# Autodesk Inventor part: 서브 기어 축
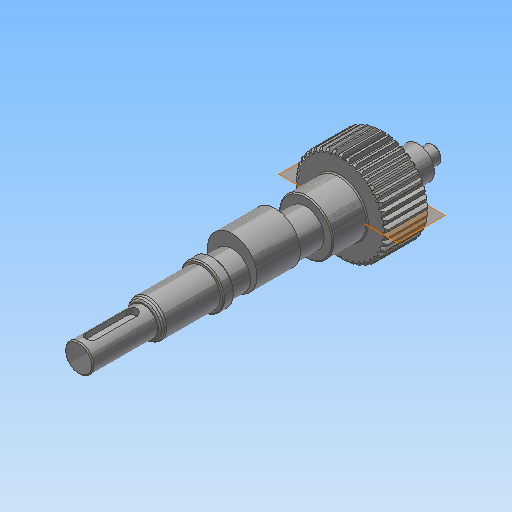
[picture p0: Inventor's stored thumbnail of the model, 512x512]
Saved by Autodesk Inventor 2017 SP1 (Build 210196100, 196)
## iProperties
Created: 2018-12
Part Number: 서브 기어 축
Material: 강철, 연강
Document SubType Name: Modeling
Designer: mduedu
Categories: <?xml version="1.0" encoding="UTF-16"?> <MemberInstance><Categories><FamilyTemplate><FamilyTemplateParameter ValueType="xs:double" Id="1" ObjectReferenceKey="da
Density: 1 g/cm^3
Appearance: 강철
Author: mduedu
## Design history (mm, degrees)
sketch "Sketch1"
  geometry: C1 r 21.3 at (0, 0)
  constraints: 1 centre point
  dimensions: "d0" = 42.6 diameter of C1 (= da_da)
extrude "Extrusion1" new body sketch "Sketch1" distance "d1" = 20 (= da_b); taper "d2" = 0 deg
workplane "Work Plane2"
sketch "Sketch2"
  geometry: C1 r 21.3 at (0, 0) reference; C2 r 20.5 at (0, 0)
  constraints: 1 centre point, 1 coincident
  dimensions: "d3" = 41 diameter of C2 (= da_dw)
feature "피치 지름" sketch "Sketch2" dims "d4" = 10, "d5" = 0
workplane "Work Plane8"
workplane "Work Plane9"
chamfer "모따기1" distance "d49" = 1; stored, may be unused: second distance "d50" = 2, angle "d51" = 45 deg
sketch "스케치3"
  geometry: C1 r 12.5 at (0, 0); 1 further point
  constraints: 1 centre point, 1 coincident
  dimensions: "d52" = 25 diameter of C1
extrude "돌출2" join sketch "스케치3" distance "d53" = 16; taper "d54" = 0 deg
sketch "스케치4"
  geometry: C1 r 8.5 at (0, 0); 1 further point
  constraints: 1 centre point, 1 coincident
  dimensions: "d55" = 17 diameter of C1
extrude "돌출3" join sketch "스케치4" distance "d56" = 105; taper "d57" = 0 deg
sketch "스케치5"
  geometry: C1 r 7.5 at (0, 0); 1 further point
  constraints: 1 centre point, 1 coincident
  dimensions: "d58" = 15 diameter of C1
extrude "돌출4" join sketch "스케치5" distance "d59" = 16; taper "d60" = 0 deg
sketch "스케치6"
  geometry: C1 r 4 at (0, 0); 1 further point
  constraints: 1 centre point, 1 coincident
  dimensions: "d61" = 8 diameter of C1
extrude "돌출5" join sketch "스케치6" distance "d62" = 7; taper "d63" = 0 deg
fillet "모깎기1" dims "d67" = 0.5
feature "스퍼 기어" dims "da_b" = 20, "da_d" = 41, "da_aw" = 31, "da_da" = 42.6, "da_df" = 39.086, "da_dw" = 41, angle "da_beta" = 0 deg, "da_lefttooth" = 0, "da_righttooth" = 0
node "작업 평면11"
sketch "스케치7"
  geometry: C1 r 11.5 at (0, 3); C2 r 8.5 at (0, 0) reference; 1 further point
  constraints: 1 centre point, 1 tangent, 1 vertical alignment
  dimensions: "d69" = 3 distance of point (0, 0) C1.centre; "d70" = 23 diameter of C1 (derived)
extrude "돌출6" join sketch "스케치7" stored distance "d71" = 20; taper "d72" = 0 deg
node "작업 평면12"
sketch "스케치8"
  geometry: C1 r 12.5 at (0, 0) reference; C2 r 10 at (0, 0); 1 further point
  constraints: 1 centre point, 1 coincident
  dimensions: "d110" = 20 diameter of C2
extrude "돌출7" join sketch "스케치8" distance "d74" = 5; taper "d75" = 0 deg
sketch "스케치14"
  geometry: L1 (-11.5, 111)-(-6.5, 111); L2 (-6.5, 111)-(-6.5, 141); L3 (-6.5, 141)-(-11.5, 141); L4 (-11.5, 141)-(-11.5, 111); L5 (8.5, 141)-(-8.5, 141) reference; L6 (0, 0)-(0, 141)
  constraints: 10 end point, 2 parallel, 1 collinear, 1 horizontal, 1 midpoint, 1 perpendicular
  dimensions: "d92" = 30 distance between parallel lines of L1 L5; "d93" = 13 diameter of L2 L6; "d95" = 5 distance of L2.end L3.end
revolve "회전2" sketch "스케치14" stored, may be unused: angle "d96" = 90 deg
chamfer "모따기4" distance "d97" = 0.5; stored, may be unused: second distance "d98" = 2, angle "d99" = 45 deg
revolve "회전1" stored, may be unused: angle "d82" = 90 deg
sketch "스케치10"
  geometry: L1 (-6.5, 117.5)-(-5, 116) reference; L2 (-6.5, 114.5)-(-5, 116) reference; 2 further points
  constraints: 1 coincident
node "작업점1"
node "작업 평면13"
sketch "스케치11"
  geometry: L1 (-2.5, 9.5)-(-2.5, -9.5); L2 (2.5, -9.5)-(2.5, 9.5); L3 (-6, 15)-(6, 15) reference; A1 r 2.5 centre (0, 9.5) between (2.5, 9.5) and (-2.5, 9.5); A2 r 2.5 centre (0, -9.5) between (-2.5, -9.5) and (2.5, -9.5); 1 further point
  constraints: 4 end point, 4 point on circle, 4 tangent, 2 centre point, 2 vertical alignment, 1 parallel
  dimensions: "d84" = 24 dimension on A2 A1; "d85" = 5 distance between parallel lines of L1 L2; "d108" = 3 distance edge to line of A1 L3
extrude "돌출8" cut sketch "스케치11" distance "d86" = 3; taper "d87" = 0 deg
sketch "스케치12" dims "d88" = 32
  geometry: C1 r 0.5 at (0, -16); 2 further points
  constraints: 2 vertical alignment, 1 centre point, 1 coincident, 2 other
  dimensions: "d89" = 1 diameter of C1
extrude "돌출9" join sketch "스케치12" distance "d90" = 0.3; taper "d91" = 0 deg
sketch "스케치13"
  geometry: C1 r 11.5 at (0, 3) reference; 1 further point
  node "절단 모서리 투영1"
sketch "스케치15"
  geometry: L1 (-8.5, 109.181)-(-7.45, 111); L2 (-8.5, 111)-(8.5, 111) reference; L3 (-8.5, 84)-(-8.5, 111) reference; L4 (0, 0)-(0, 111); L5 (-7.45, 111)-(-8.5, 111); L6 (-8.5, 109.181)-(-8.5, 111)
  constraints: 8 end point, 2 collinear, 2 point on line, 1 midpoint
  dimensions: "d103" = 14.9 diameter of L1.end L4; "d104" = 30 deg angle of L3 L1
revolve "회전3" sketch "스케치15" stored, may be unused: angle "d105" = 90 deg
fillet "모깎기2" dims "d106" = 2
fillet "모깎기3" dims "d107" = 1
chamfer "모따기5" distance "d112" = 0.5; stored, may be unused: second distance "d113" = 2, angle "d114" = 45 deg
body "Solid1"
body "Srf1"
node "투영된 루프1"
sketch "스케치9"
  geometry: L1 (0, 138.97)-(0, 0); L2 (-6.5, 116)-(0, 116); L3 (-6.5, 116)-(-6.5, 114.5); L4 (-6.5, 114.5)-(-5, 116); L5 (-5, 116)-(-6.5, 116); L6 (-6, 141)-(6, 141) reference
  constraints: 10 end point, 2 point on line, 1 collinear, 1 vertical
  dimensions: "d80" = 3 diameter of L3.end L2; "d100" = 25 distance between parallel lines of L6 L2; "d101" = 6.5 distance between parallel lines of L1 L3; "d102" = 45 deg angle of L4 L3
other parameters: "d16" = 31 (= da_aw), "d17" = 0, "d34" = 0.76624 (computed from da_z), "d39" = 0, "d41" = 0, "d43" = 31 (= da_aw), "d46" = 31 (= da_aw), "d47" = 0, "d48" = 0
